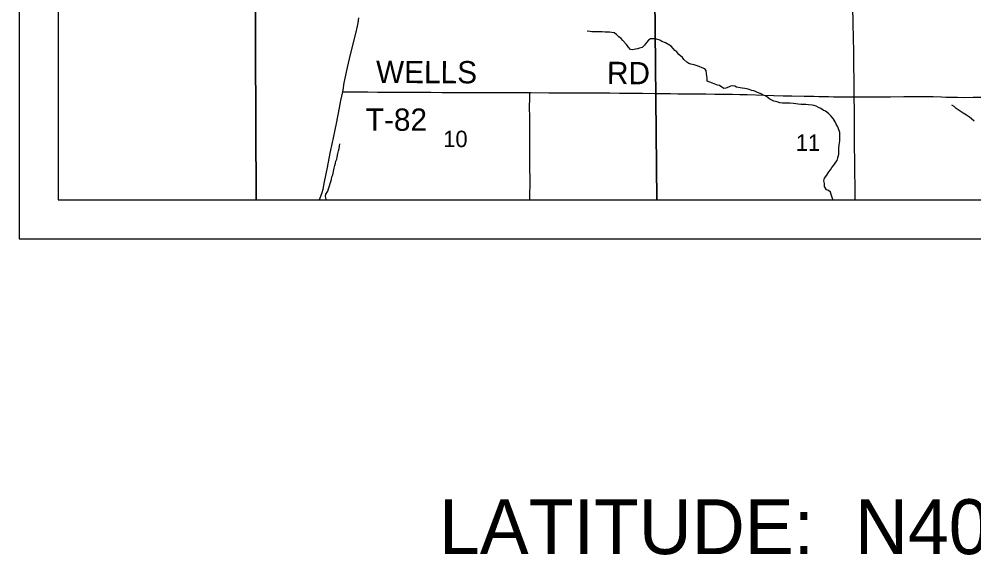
# Model space of a CAD drawing. Extents: x 0 to 34, y 0 to 22.
# Drawn here: x 2 to 4.435, y 13.194 to 14.561 of the extents above; entities that cross this region are included whole.
import ezdxf

# ---------------------------------------------------------------- set-up
doc = ezdxf.new("R2010")
doc.units = 0
for name, color, linetype in [('Default', 7, 'Continuous'), ('GM_X_County_Road', 7, 'Continuous'), ('GM_X_Minor_River', 7, 'Continuous'), ('GM_X_Section_Text', 7, 'Continuous'), ('GM_X_State_Route', 7, 'Continuous'), ('GM_X_Township_Road', 7, 'Continuous'), ('GM_X_Township_Road_Text', 7, 'Continuous'), ('SH_Data', 7, 'Continuous'), ('SH_Text', 7, 'Continuous')]:
    doc.layers.add(name, color=color, linetype=linetype)

msp = doc.modelspace()

# ---------------------------------------------------------------- linework, layer by layer
at = {"layer": 'Default'}
for points in [[(2.1, 14.8606), (2.1, 14.1), (2.605, 14.1), (2.6012, 14.88)], [(2.605, 14.1), (3.6266, 14.1), (3.6188, 14.8751), (2.6012, 14.88)], [(3.6266, 14.1), (4.6336, 14.1), (4.6247, 14.8633), (4.1707, 14.8603), (3.6188, 14.8751)]]:
    msp.add_lwpolyline(points, close=True, dxfattribs=at)
at = {"layer": 'GM_X_County_Road'}
for points in [[(4.1301, 14.3621), (4.1301, 14.365), (4.1301, 14.393), (4.1298, 14.4116), (4.1293, 14.4363), (4.129, 14.4797), (4.1284, 14.5107), (4.1275, 14.551), (4.1269, 14.5913)], [(2.8256, 14.3751), (2.8263, 14.3791), (2.8296, 14.3982), (2.8377, 14.437), (2.8428, 14.4592), (2.8513, 14.4944), (2.8592, 14.5241), (2.8634, 14.5423), (2.865, 14.5515), (2.8664, 14.5639)], [(2.7658, 14.1), (2.7661, 14.1006), (2.77, 14.1092), (2.773, 14.1181), (2.7754, 14.1272), (2.7793, 14.1454), (2.7866, 14.1821), (2.7938, 14.2187), (2.7998, 14.2459), (2.8023, 14.2578), (2.8092, 14.2942), (2.8172, 14.334), (2.8211, 14.3528), (2.8256, 14.3751)], [(4.133, 14.1), (4.1329, 14.1077), (4.1327, 14.118), (4.1325, 14.1294), (4.1319, 14.1757), (4.1317, 14.2005), (4.1313, 14.2346), (4.1311, 14.2656), (4.131, 14.2843), (4.1305, 14.3277), (4.1301, 14.3621)]]:
    msp.add_lwpolyline(points, dxfattribs=at)
at = {"layer": 'GM_X_Minor_River'}
for points in [[(3.703, 14.4506), (3.6953, 14.4575), (3.6923, 14.4628), (3.6831, 14.47), (3.6777, 14.4769), (3.6728, 14.4807), (3.6686, 14.486), (3.6636, 14.4917), (3.6491, 14.4997), (3.6395, 14.5039), (3.6342, 14.5066), (3.6288, 14.5085), (3.6231, 14.51), (3.6158, 14.5104), (3.6105, 14.51), (3.6055, 14.5066), (3.6002, 14.5013), (3.5953, 14.494), (3.5892, 14.4879), (3.5823, 14.4864), (3.5774, 14.4849), (3.5724, 14.4842), (3.5655, 14.4826), (3.5598, 14.4834), (3.5533, 14.4895), (3.5491, 14.496), (3.5403, 14.5058), (3.5361, 14.5108), (3.53, 14.515), (3.5235, 14.5211), (3.5177, 14.5256), (3.5116, 14.5268), (3.5059, 14.5275), (3.4998, 14.5272), (3.4948, 14.5275), (3.4876, 14.5279), (3.4796, 14.5279), (3.4731, 14.5283), (3.467, 14.5283), (3.4612, 14.5283), (3.4563, 14.5287), (3.4494, 14.5295)], [(4.0758, 14.1), (4.0755, 14.1006), (4.0728, 14.1078), (4.0713, 14.1135), (4.0694, 14.1188), (4.0644, 14.1234), (4.0594, 14.1249), (4.0545, 14.1337), (4.0541, 14.1413), (4.0525, 14.1481), (4.054, 14.1553), (4.0601, 14.1626), (4.0658, 14.1709), (4.07, 14.1759), (4.073, 14.1823), (4.0784, 14.188), (4.0829, 14.1953), (4.0864, 14.2002), (4.0886, 14.2067), (4.0909, 14.2162), (4.0909, 14.2302), (4.0916, 14.2401), (4.0924, 14.2454), (4.0931, 14.2504), (4.0935, 14.2588), (4.0935, 14.2637), (4.0934, 14.2713), (4.0884, 14.2861), (4.0842, 14.2926), (4.0819, 14.2987), (4.0769, 14.3067), (4.0708, 14.3135), (4.0643, 14.32), (4.0567, 14.3257), (4.0513, 14.3284), (4.0448, 14.3329), (4.0391, 14.3352), (4.0334, 14.3386), (4.028, 14.3402), (4.0231, 14.3413), (4.0139, 14.3421), (4.0066, 14.3428), (4.0013, 14.3432), (3.9952, 14.3432), (3.9872, 14.344), (3.9815, 14.3444), (3.975, 14.3455), (3.9658, 14.3459), (3.9471, 14.3459), (3.9402, 14.3471), (3.9337, 14.3493), (3.9253, 14.3516), (3.92, 14.3539), (3.9146, 14.3562), (3.9066, 14.3634), (3.899, 14.3669), (3.8929, 14.3703), (3.8879, 14.3718), (3.8745, 14.3775), (3.8692, 14.3787), (3.8596, 14.3817), (3.8508, 14.3836), (3.8444, 14.3848), (3.8394, 14.3855), (3.8302, 14.387), (3.8253, 14.3897), (3.8192, 14.3905), (3.8142, 14.3893), (3.8092, 14.3874), (3.8028, 14.3848), (3.7974, 14.384), (3.7924, 14.3867), (3.7867, 14.3916), (3.7817, 14.3924), (3.7768, 14.3939), (3.7688, 14.397), (3.7615, 14.3996), (3.755, 14.4027), (3.755, 14.4091), (3.7546, 14.416), (3.7538, 14.4213), (3.7523, 14.4293), (3.7488, 14.4342), (3.7423, 14.4365), (3.7343, 14.4396), (3.7221, 14.4438), (3.7137, 14.4457), (3.7087, 14.4476), (3.703, 14.4506)], [(4.4365, 14.3004), (4.4292, 14.3065), (4.4242, 14.3107), (4.4166, 14.3152), (4.4078, 14.3206), (4.3982, 14.3278), (4.3906, 14.3327), (4.3852, 14.3381), (4.3795, 14.3411)], [(2.7835, 14.1), (2.7833, 14.1013), (2.7818, 14.1078), (2.7825, 14.1142), (2.7871, 14.1215), (2.7893, 14.1275), (2.792, 14.1355), (2.7943, 14.1435), (2.7965, 14.1519), (2.7981, 14.158), (2.8, 14.1637), (2.8018, 14.1717), (2.8033, 14.18), (2.8052, 14.1872), (2.8071, 14.1933), (2.8083, 14.1986), (2.8102, 14.2036), (2.8109, 14.2085), (2.8132, 14.2177), (2.8151, 14.2245), (2.8166, 14.2302), (2.8173, 14.2363), (2.8185, 14.2427)]]:
    msp.add_lwpolyline(points, dxfattribs=at)
at = {"layer": 'GM_X_State_Route'}
msp.add_lwpolyline([(4.6144, 15.8751), (3.6011, 15.8701), (2.7891, 15.8734), (2.5819, 15.8726), (2.1, 15.8695), (2.1, 14.1), (5.6455, 14.1)], dxfattribs=at)
at = {"layer": 'GM_X_Township_Road'}
for points in [[(2.8256, 14.3751), (2.8315, 14.3748), (2.8489, 14.3748), (2.8706, 14.3749), (2.8892, 14.3747), (2.914, 14.3744), (2.9668, 14.374), (3.004, 14.3741), (3.0226, 14.374), (3.0506, 14.3739), (3.0785, 14.3738), (3.1157, 14.3735), (3.1467, 14.3734), (3.1746, 14.3733), (3.1994, 14.3733), (3.2304, 14.3732), (3.2739, 14.3733), (3.3026, 14.3732)], [(3.3031, 14.1), (3.3031, 14.1027), (3.3032, 14.1493), (3.3029, 14.1834), (3.3027, 14.2145), (3.3027, 14.2425), (3.3028, 14.2735), (3.3025, 14.2921), (3.3024, 14.3076), (3.3023, 14.3386), (3.3025, 14.3567), (3.3026, 14.3707), (3.3026, 14.3732)], [(3.3026, 14.3732), (3.305, 14.3732), (3.3515, 14.3727), (3.3981, 14.3726), (3.4167, 14.3726), (3.4508, 14.3727), (3.4725, 14.3726), (3.5066, 14.3722), (3.5315, 14.3719), (3.5749, 14.3715), (3.5904, 14.3714), (3.6214, 14.3712), (3.6616, 14.3708), (3.6801, 14.3704), (3.7019, 14.37), (3.7236, 14.3698), (3.7515, 14.3696), (3.775, 14.3695), (3.7949, 14.3693), (3.8197, 14.3691), (3.8382, 14.3686), (3.8568, 14.3681), (3.9003, 14.367), (3.9251, 14.3661), (3.9487, 14.3653), (3.9708, 14.3647), (4.0026, 14.3637), (4.0274, 14.3638), (4.0399, 14.3636), (4.0554, 14.3631), (4.0647, 14.3628), (4.077, 14.3626), (4.0894, 14.3625), (4.108, 14.3623), (4.1301, 14.3621)], [(4.1301, 14.3621), (4.1514, 14.3622), (4.1915, 14.3621), (4.2224, 14.3622), (4.2569, 14.3628), (4.2817, 14.3636), (4.3034, 14.3635), (4.3314, 14.3629), (4.3531, 14.362), (4.3647, 14.3617), (4.381, 14.3611), (4.3934, 14.3611), (4.4089, 14.3609), (4.4337, 14.3612), (4.4832, 14.3614), (4.5049, 14.3616), (4.5235, 14.3612), (4.5616, 14.3597), (4.5675, 14.3587), (4.5723, 14.3579)]]:
    msp.add_lwpolyline(points, dxfattribs=at)
at = {"layer": 'SH_Data'}
for p, q in [((2, 21), (2, 14)), ((2.1, 20.9), (2.1, 14.1)), ((2.1, 14.1), (8.9, 14.1)), ((2.1, 14.1), (2.1, 14.1)), ((2, 14), (9, 14))]:
    msp.add_line(p, q, dxfattribs=at)

# ---------------------------------------------------------------- texts
at = {"layer": 'GM_X_Section_Text'}
for s, p in [('10', (3.0818, 14.2341)), ('11', (3.981, 14.2245))]:
    msp.add_text(s, height=0.04186, rotation=0, dxfattribs=at).set_placement(p)
at = {"layer": 'GM_X_Township_Road_Text'}
for s, rotation, p in [('WELLS', 359.7945, (2.9104, 14.3976)), ('RD', 359.5134, (3.4993, 14.3951)), ('T-82', 0, (2.8843, 14.2758))]:
    msp.add_text(s, height=0.05682, rotation=rotation, dxfattribs=at).set_placement(p)
at = {"layer": 'SH_Text'}
msp.add_text('LATITUDE:  N40°45\'21"     LONGITUDE:  S81°59\'48"', height=0.14, dxfattribs=at).set_placement((3.071, 13.1958))

doc.saveas('drawing.dxf')
